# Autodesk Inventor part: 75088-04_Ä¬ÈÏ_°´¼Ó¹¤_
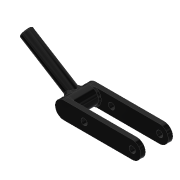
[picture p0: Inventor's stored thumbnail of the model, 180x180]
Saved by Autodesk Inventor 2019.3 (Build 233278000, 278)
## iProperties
Created: 2010-06
Part Number: 75088-04_Ä¬ÈÏ_°´¼Ó¹¤_
Material: Ogólny
Document SubType Name: Modeling
Designer: CADENGINEERING4
Density: 1 g/cm^3
Appearance: Gładki — czarny
Author: CADENGINEERING4
Revision Number: ÈÎºÎ
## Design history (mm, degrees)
feature "NONE"
feature "NONE:1"
feature "NONE:2"
feature "NONE:3"
feature "NONE:4"
feature "NONE:5"
feature "NONE:6"
node "Bryła1"
node "Bryła2"
node "Bryła3"
node "Bryła4"
node "Bryła5"
node "Bryła6"
node "Bryła7"
